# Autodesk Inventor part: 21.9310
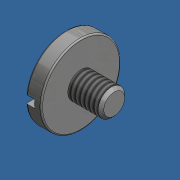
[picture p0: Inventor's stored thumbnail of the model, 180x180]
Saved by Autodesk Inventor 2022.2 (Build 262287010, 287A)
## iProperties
Part Number: 21.9310
Material: Stainless Steel
Document SubType Name: Modeling
Designer: amoles
Appearance: Zinc
Description: MAGNETIC CATCH 30 SCREW
Stock Number: 21.9310 MAGNETIC CATCH 30 SCREW
Mass: 2.42055 g
Surface Area: 3.93915 cm^2
Volume: 0.302569 cm^3
Density: 8 g/cm^3
Author: amoles
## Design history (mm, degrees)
feature "093094-2"
thread "Thread1" dims "d0" = 4.57, "d1" = 0
body "Solid1"
